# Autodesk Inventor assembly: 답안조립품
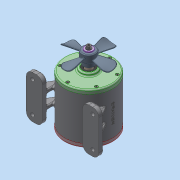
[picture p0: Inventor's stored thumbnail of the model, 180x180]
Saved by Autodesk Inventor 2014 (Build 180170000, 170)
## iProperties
Created: 2024-02
Part Number: 답안조립품
Document SubType Name: Assembly
Designer: dg
Mass: 3108.48 g
Surface Area: 2333.46 cm^2
Volume: 963.013 cm^3
Density: 3.22787 g/cm^3
Author: dg
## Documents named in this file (20)
- C:\Users\dg\Desktop\640204V1007\답안조립품.iam
- C:\Users\dg\Desktop\640204V1007\본체.ipt
- C:\Users\dg\Desktop\640204V1007\메인 기어 축.ipt
- C:\Users\dg\Desktop\640204V1007\서브 기어 축.ipt
- C:\Users\dg\Desktop\640204V1007\앞커버.ipt
- C:\Users\dg\Desktop\640204V1007\뒷커버.ipt
- C:\Users\dg\Desktop\640204V1007\베어링 608.ipt
- C:\Users\dg\Desktop\640204V1007\오일 실 8 22 7.ipt
- C:\Users\dg\Desktop\640204V1007\오일 실 17 30 8.ipt
- C:\Users\dg\Desktop\640204V1007\베어링 6903.ipt
- C:\Users\dg\Desktop\640204V1007\슬라이더.ipt
- C:\Users\dg\Desktop\640204V1007\스프링.ipt
- C:\Users\dg\Desktop\640204V1007\부시.ipt
- C:\Users\dg\Desktop\640204V1007\키 5 x 5 x 24.ipt
- C:\Users\dg\Desktop\640204V1007\팬날개.ipt
- 팬날개.ipt
- C:\Users\dg\Desktop\640204V1007\스프링 와셔 M6.ipt
- C:\Users\dg\Desktop\640204V1007\육각 소켓 머리 볼트 M6 x 12.ipt
- C:\Users\dg\Desktop\640204V1007\앤드 캡.ipt
- C:\Users\dg\Desktop\640204V1007\육각 소켓 머리 볼트 M4 x 12.ipt
